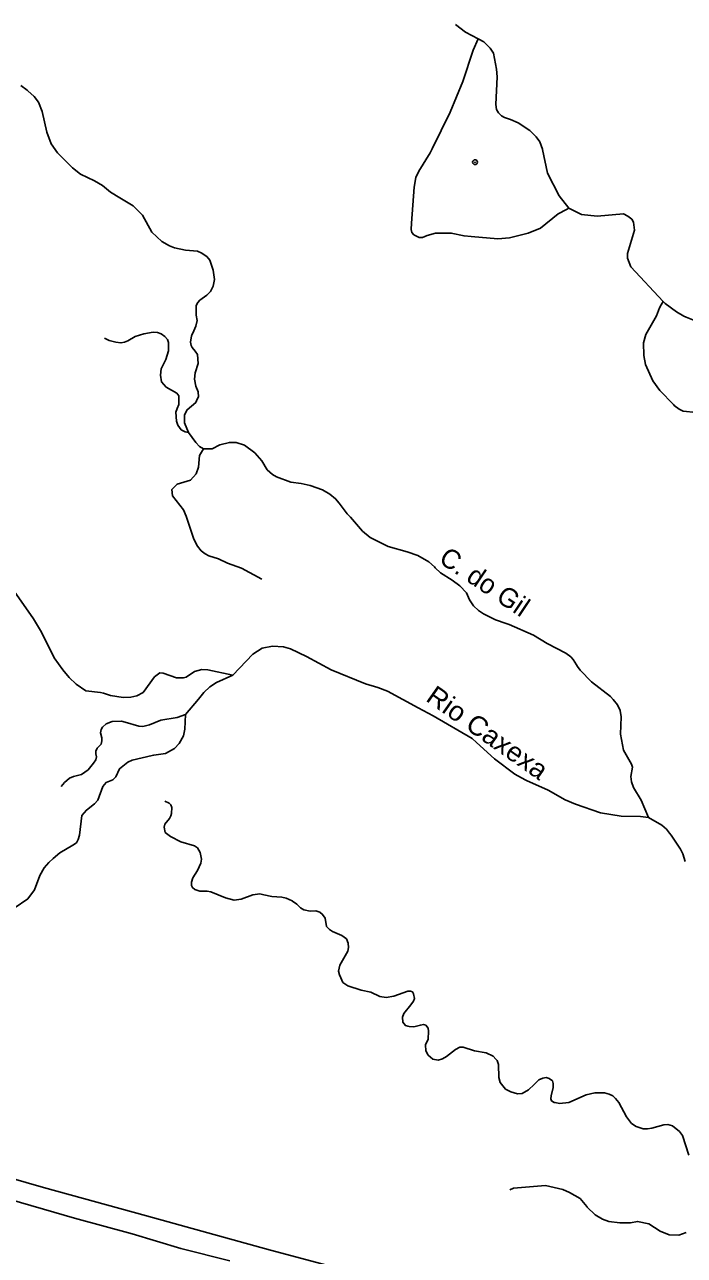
# Model space of a CAD drawing. Extents: x 267.7 to 296, y 7537.7 to 7565.8.
# Drawn here: x 270.43 to 273.16, y 7560.4 to 7565.5 of the extents above; entities that cross this region are included whole.
import ezdxf
from ezdxf.enums import TextEntityAlignment as Align

# ---------------------------------------------------------------- set-up
doc = ezdxf.new("R2010")
doc.units = 0
doc.header["$LTSCALE"] = 0.04
doc.header["$PDMODE"] = 32
doc.header["$PDSIZE"] = 0.02
doc.layers.add('1', color=7, linetype='Continuous', lineweight=25)
doc.layers.add('7', color=7, linetype='Continuous', lineweight=25)
doc.layers.add('54', color=7, linetype='Continuous')
doc.layers.add('61', color=7, linetype='Continuous')

msp = doc.modelspace()

# ---------------------------------------------------------------- linework, layer by layer
at = {"layer": '1'}
for points in [[(269.2121, 7561.0128), (269.2305, 7560.9925), (269.2633, 7560.9712), (269.4053, 7560.9017), (269.5415, 7560.8437), (269.6371, 7560.8099), (269.7646, 7560.778), (269.8438, 7560.7636), (269.9134, 7560.7578), (270.0882, 7560.7597), (270.2099, 7560.7481), (270.2891, 7560.7394), (270.3664, 7560.722), (270.5103, 7560.6815), (270.9372, 7560.5636), (271.1913, 7560.4931), (271.4501, 7560.4207), (271.787, 7560.3318)], [(270.3281, 7560.6436), (270.6385, 7560.5546), (270.8781, 7560.4889), (271.0795, 7560.4289), (271.2817, 7560.3773)]]:
    msp.add_lwpolyline(points, dxfattribs=at)
at = {"layer": '54'}
msp.add_point((272.2974, 7564.9283), dxfattribs=at)
at = {"layer": '7'}
for points in [[(272.2171, 7565.4981), (272.2574, 7565.4673), (272.3106, 7565.4393)], [(272.3106, 7565.4393), (272.2897, 7565.3918), (272.2464, 7565.2624), (272.1946, 7565.1352), (272.1198, 7564.9839), (272.1112, 7564.9666), (272.0648, 7564.8905), (272.0527, 7564.8651), (272.0452, 7564.8253), (272.0349, 7564.6754), (272.0329, 7564.6498), (272.036, 7564.6364), (272.0442, 7564.6272), (272.0657, 7564.6169), (272.08, 7564.6166), (272.0993, 7564.6251), (272.1343, 7564.6344), (272.1991, 7564.6348), (272.2518, 7564.6226), (272.2815, 7564.62), (272.3922, 7564.6101), (272.4407, 7564.6154), (272.5179, 7564.6345), (272.5681, 7564.6548), (272.6414, 7564.7145), (272.6759, 7564.7318), (272.6857, 7564.738)], [(272.3106, 7565.4393), (272.3342, 7565.4269), (272.3601, 7565.3999), (272.3733, 7565.3793), (272.3869, 7565.3138), (272.3893, 7565.2823), (272.3839, 7565.1671), (272.386, 7565.1465), (272.3942, 7565.1332), (272.4065, 7565.1209), (272.4188, 7565.1137), (272.4445, 7565.1055), (272.4763, 7565.0908), (272.5241, 7565.0596), (272.5511, 7565.0332), (272.5657, 7565.0123), (272.5772, 7564.9815), (272.5774, 7564.9811), (272.5978, 7564.8823), (272.6463, 7564.7888), (272.6857, 7564.738)], [(270.4159, 7565.2456), (270.4429, 7565.2259), (270.4455, 7565.224), (270.4716, 7565.2), (270.4894, 7565.1764), (270.5049, 7565.1377), (270.5236, 7565.0528), (270.5415, 7565.0039), (270.5679, 7564.9668), (270.6301, 7564.9053), (270.6639, 7564.8791), (270.7216, 7564.851), (270.7545, 7564.8314), (270.7881, 7564.8035), (270.8268, 7564.7805), (270.8815, 7564.7479), (270.9201, 7564.7085), (270.9591, 7564.639), (271.0003, 7564.6001), (271.0325, 7564.5815), (271.0527, 7564.5739), (271.0991, 7564.5638), (271.1477, 7564.5597), (271.1509, 7564.5584), (271.1635, 7564.5533), (271.1863, 7564.5372), (271.1995, 7564.5229), (271.2132, 7564.4805), (271.2179, 7564.4424), (271.2128, 7564.4147), (271.2015, 7564.3926), (271.1866, 7564.3775), (271.1571, 7564.3561), (271.1491, 7564.347), (271.1431, 7564.3346), (271.143, 7564.2946), (271.1461, 7564.2725), (271.1409, 7564.2484), (271.1336, 7564.2293), (271.1247, 7564.211), (271.1236, 7564.2087), (271.1191, 7564.1825), (271.1214, 7564.1694), (271.1266, 7564.1602), (271.1389, 7564.1448), (271.1477, 7564.1313), (271.1509, 7564.0946), (271.1385, 7564.056), (271.1358, 7564.0292), (271.1408, 7564.0007), (271.1508, 7563.9774), (271.1516, 7563.9566), (271.1472, 7563.9462), (271.1416, 7563.9329), (271.1055, 7563.9028), (271.0941, 7563.882), (271.0936, 7563.8484), (271.1106, 7563.8087)], [(272.6857, 7564.738), (272.719, 7564.721), (272.7387, 7564.711), (272.8037, 7564.705), (272.9117, 7564.7137), (272.93, 7564.7052), (272.9469, 7564.6915), (272.9531, 7564.6794), (272.9575, 7564.646), (272.9288, 7564.5494), (272.9291, 7564.5303), (272.9426, 7564.4949), (273.0769, 7564.3511)], [(273.0769, 7564.3511), (273.0675, 7564.3377), (273.0609, 7564.3243), (273.0491, 7564.2921), (273.0049, 7564.2149), (272.9943, 7564.1795), (272.9966, 7564.1269), (273.0033, 7564.0905), (273.0337, 7564.0219), (273.0626, 7563.9822), (273.1194, 7563.9241), (273.1225, 7563.9209), (273.1427, 7563.905), (273.1599, 7563.8968), (273.2137, 7563.8919)], [(273.0769, 7564.3511), (273.0852, 7564.3422), (273.1311, 7564.3079), (273.1617, 7564.291), (273.1713, 7564.2857), (273.2409, 7564.2583), (273.3691, 7564.23), (273.5033, 7564.2158), (273.5828, 7564.196), (273.6844, 7564.1868)], [(270.7624, 7564.1988), (270.7817, 7564.1899), (270.8104, 7564.1827), (270.831, 7564.1797), (270.8464, 7564.1827), (270.8592, 7564.1885), (270.89, 7564.2065), (270.9264, 7564.2176), (270.9646, 7564.2238), (270.9829, 7564.2228), (270.9971, 7564.2172), (271.0127, 7564.2064), (271.0239, 7564.194), (271.0278, 7564.1815), (271.028, 7564.1469), (271.0175, 7564.1102), (270.9977, 7564.0719), (270.9946, 7564.0454), (270.999, 7564.0185), (271.0177, 7563.9968), (271.0632, 7563.9713), (271.0708, 7563.96), (271.0711, 7563.925), (271.0645, 7563.9083), (271.0582, 7563.8922), (271.0607, 7563.8556), (271.066, 7563.8385), (271.0808, 7563.8193), (271.0965, 7563.8115), (271.1106, 7563.8087)], [(271.1106, 7563.8087), (271.1106, 7563.8086), (271.1406, 7563.7673), (271.1568, 7563.7503), (271.1734, 7563.7415)], [(271.1734, 7563.7415), (271.2086, 7563.7406), (271.2409, 7563.7577), (271.2806, 7563.7675), (271.3086, 7563.7675), (271.3424, 7563.7562), (271.3853, 7563.7246), (271.414, 7563.6911), (271.4372, 7563.6544), (271.4583, 7563.6347), (271.4747, 7563.6249), (271.5348, 7563.6032), (271.5772, 7563.5967), (271.6145, 7563.5884), (271.6661, 7563.5705), (271.6957, 7563.5531), (271.7198, 7563.534), (271.7348, 7563.5163), (271.7673, 7563.4716), (271.7814, 7563.4581), (271.8316, 7563.3996), (271.863, 7563.3731), (271.9374, 7563.3367), (272.0167, 7563.3147), (272.0599, 7563.2985), (272.1058, 7563.2723), (272.1294, 7563.2518), (272.1327, 7563.2485), (272.1538, 7563.2275), (272.2032, 7563.1964), (272.234, 7563.1727), (272.2615, 7563.1437), (272.2749, 7563.1154), (272.2917, 7563.0902), (272.3116, 7563.071), (272.3329, 7563.0569), (272.3817, 7563.0324), (272.4262, 7563.0176), (272.4382, 7563.0136), (272.5394, 7562.9694), (272.5965, 7562.9345), (272.6739, 7562.8943), (272.6939, 7562.8792), (272.7043, 7562.8684), (272.7182, 7562.8462), (272.7223, 7562.8397), (272.7321, 7562.824), (272.7798, 7562.7757), (272.8585, 7562.7149), (272.8689, 7562.7025), (272.8874, 7562.6803), (272.8982, 7562.6565), (272.9025, 7562.6308), (272.9001, 7562.5582), (272.9127, 7562.4925), (272.9451, 7562.434), (272.9488, 7562.4218), (272.9424, 7562.3833), (272.9455, 7562.3614), (272.9533, 7562.338)], [(271.4151, 7563.2004), (271.3301, 7563.246), (271.2725, 7563.2677), (271.2349, 7563.2857), (271.1956, 7563.2974), (271.1792, 7563.3053), (271.1638, 7563.3181), (271.1487, 7563.3378), (271.1332, 7563.3671), (271.1017, 7563.462), (271.0903, 7563.4881), (271.0448, 7563.5458), (271.0413, 7563.5722), (271.0635, 7563.595), (271.1195, 7563.6109), (271.1421, 7563.6366), (271.1525, 7563.6653), (271.1558, 7563.7127), (271.1734, 7563.7415)], [(270.3497, 7563.2064), (270.4684, 7563.0369), (270.5016, 7562.9819), (270.5552, 7562.8746), (270.59, 7562.8247), (270.6164, 7562.7932), (270.6455, 7562.7662), (270.6863, 7562.739), (270.7471, 7562.7309), (270.759, 7562.7293), (270.7874, 7562.7189), (270.8409, 7562.711), (270.8719, 7562.7125), (270.8972, 7562.7182), (270.9227, 7562.7317), (270.9701, 7562.7958), (270.9915, 7562.8127), (271.0057, 7562.8122), (271.0612, 7562.7925), (271.0903, 7562.7924), (271.1011, 7562.7955), (271.1362, 7562.8184), (271.1656, 7562.8273)], [(271.294, 7562.8034), (271.3777, 7562.8898), (271.4153, 7562.9148), (271.4586, 7562.9231), (271.5049, 7562.92), (271.5339, 7562.912), (271.5997, 7562.8812), (271.7012, 7562.8252), (271.8444, 7562.767), (271.8953, 7562.7519), (271.9354, 7562.7368), (272.0622, 7562.668), (272.1236, 7562.6347), (272.2859, 7562.5407), (272.3041, 7562.5242), (272.3785, 7562.4569), (272.4628, 7562.3934), (272.5048, 7562.3694), (272.5103, 7562.3663), (272.6, 7562.3271), (272.6705, 7562.2862), (272.7136, 7562.2685), (272.8168, 7562.2334), (272.9029, 7562.2188), (272.9828, 7562.2177), (273.0159, 7562.2134)], [(271.0978, 7562.6403), (271.1523, 7562.7034), (271.1743, 7562.7319), (271.1998, 7562.7551), (271.2272, 7562.773), (271.294, 7562.8034)], [(271.1656, 7562.8273), (271.1908, 7562.825), (271.294, 7562.8034)], [(270.3884, 7561.8381), (270.445, 7561.8765), (270.4738, 7561.9138), (270.4952, 7561.974), (270.5131, 7562.0052), (270.532, 7562.0272), (270.5498, 7562.0441), (270.578, 7562.0674), (270.6318, 7562.0988), (270.6468, 7562.109), (270.6539, 7562.1232), (270.6596, 7562.1403), (270.6698, 7562.2217), (270.6884, 7562.2444), (270.7218, 7562.2707), (270.7352, 7562.2858), (270.7554, 7562.3424), (270.7693, 7562.3583), (270.7979, 7562.37), (270.8096, 7562.3815), (270.8249, 7562.4159), (270.8593, 7562.4426), (270.8778, 7562.4514), (270.961, 7562.4709), (270.9666, 7562.4722), (271.0161, 7562.479), (271.0533, 7562.5), (271.0725, 7562.5208), (271.0895, 7562.5513), (271.0958, 7562.5801), (271.0978, 7562.6403)], [(270.5836, 7562.3424), (270.598, 7562.3588), (270.6186, 7562.376), (270.6348, 7562.3834), (270.6681, 7562.392), (270.695, 7562.4105), (270.717, 7562.4386), (270.7273, 7562.4532), (270.7304, 7562.4656), (270.7273, 7562.4779), (270.7273, 7562.4881), (270.7324, 7562.5004), (270.7488, 7562.5179), (270.7519, 7562.5306), (270.7519, 7562.5438), (270.7464, 7562.5641), (270.7488, 7562.5786), (270.7546, 7562.5883), (270.7698, 7562.6018), (270.7946, 7562.6119), (270.8333, 7562.6127), (270.8488, 7562.608), (270.9048, 7562.5913), (270.9213, 7562.5905), (270.949, 7562.5981), (270.9962, 7562.6172), (271.0637, 7562.6281), (271.0978, 7562.6403)], [(272.9533, 7562.338), (272.9854, 7562.2848), (273.0159, 7562.2134)], [(271.0132, 7562.2812), (271.0311, 7562.2729), (271.0373, 7562.2664), (271.0414, 7562.2551), (271.0403, 7562.2305), (271.0383, 7562.2202), (271.0321, 7562.21), (271.0122, 7562.1856), (271.0096, 7562.174), (271.0139, 7562.1521), (271.0357, 7562.1347), (271.0794, 7562.1123), (271.1362, 7562.0967), (271.1485, 7562.0877), (271.1592, 7562.0687), (271.1653, 7562.041), (271.1625, 7562.0243), (271.1625, 7562.0242), (271.1475, 7561.9938), (271.1291, 7561.9634), (271.1239, 7561.9455), (271.1239, 7561.9324), (271.1277, 7561.923), (271.1366, 7561.9148), (271.1577, 7561.9089), (271.1882, 7561.9082), (271.203, 7561.9064), (271.2637, 7561.8806), (271.3006, 7561.8715), (271.3294, 7561.8753), (271.3779, 7561.8939), (271.4056, 7561.897), (271.4222, 7561.8938), (271.456, 7561.8858), (271.4973, 7561.8834), (271.5156, 7561.8795), (271.54, 7561.8684), (271.5415, 7561.8674), (271.559, 7561.8553), (271.575, 7561.8392), (271.5887, 7561.8314), (271.6149, 7561.8258), (271.6387, 7561.8271), (271.6552, 7561.822), (271.6663, 7561.8123), (271.6767, 7561.7969), (271.6828, 7561.7625), (271.6952, 7561.7501), (271.7076, 7561.7408), (271.7462, 7561.7254), (271.7654, 7561.7107), (271.7722, 7561.6927), (271.7734, 7561.6746), (271.7702, 7561.6595), (271.7376, 7561.602), (271.7322, 7561.5777), (271.7363, 7561.5613), (271.7414, 7561.5496), (271.7498, 7561.5306), (271.7712, 7561.5167), (271.8265, 7561.4984), (271.8663, 7561.4899), (271.9031, 7561.4728), (271.9296, 7561.4682), (271.9613, 7561.4732), (272.0191, 7561.4948), (272.03, 7561.4946), (272.0382, 7561.4908), (272.0431, 7561.4833), (272.0461, 7561.4642), (272.0421, 7561.4535), (272.0322, 7561.4381), (272.0031, 7561.4014), (271.9976, 7561.3867), (271.9984, 7561.3653), (272.0093, 7561.3519), (272.0194, 7561.3492), (272.0247, 7561.3478), (272.0437, 7561.3465), (272.0709, 7561.3539), (272.0846, 7561.356), (272.0934, 7561.3529), (272.1027, 7561.3416), (272.1053, 7561.3288), (272.1029, 7561.2958), (272.0926, 7561.2714), (272.0938, 7561.2475), (272.1035, 7561.2294), (272.1232, 7561.213), (272.1447, 7561.2091), (272.1633, 7561.2143), (272.1793, 7561.2233), (272.2165, 7561.2532), (272.2351, 7561.2616), (272.2489, 7561.2618)], [(273.0159, 7562.2134), (273.0708, 7562.1818), (273.0901, 7562.1648), (273.1025, 7562.1494), (273.1089, 7562.1399), (273.1476, 7562.0826), (273.1578, 7562.0629)], [(273.1578, 7562.0629), (273.1673, 7562.031)], [(272.2489, 7561.2618), (272.2949, 7561.2475), (272.3431, 7561.2394), (272.3724, 7561.2247), (272.3835, 7561.213), (272.3891, 7561.2071)], [(272.3891, 7561.2071), (272.3941, 7561.19), (272.3958, 7561.1361), (272.4017, 7561.116), (272.424, 7561.0882), (272.4455, 7561.0774), (272.4736, 7561.0696), (272.493, 7561.0697), (272.5187, 7561.0853), (272.542, 7561.1077), (272.5621, 7561.127), (272.5784, 7561.1334), (272.5923, 7561.1363), (272.6048, 7561.1325), (272.6179, 7561.1227), (272.6215, 7561.1115), (272.6214, 7561.0952), (272.6128, 7561.0604), (272.6118, 7561.0482), (272.6118, 7561.0481), (272.6138, 7561.0399), (272.6251, 7561.0337), (272.6291, 7561.0328), (272.6474, 7561.0288), (272.6851, 7561.0326), (272.7581, 7561.0652), (272.7934, 7561.0728), (272.833, 7561.0727)], [(272.833, 7561.0727), (272.853, 7561.0676), (272.8674, 7561.0604), (272.8793, 7561.0495), (272.8922, 7561.0325), (272.9246, 7560.9732), (272.9458, 7560.9464), (272.9652, 7560.9332), (272.9939, 7560.9244), (273.0109, 7560.9235), (273.0295, 7560.927), (273.0788, 7560.941), (273.0963, 7560.9413), (273.1147, 7560.9362), (273.1439, 7560.9134), (273.157, 7560.8968), (273.1826, 7560.8146)], [(272.4413, 7560.6707), (272.4572, 7560.6783), (272.5885, 7560.6889), (272.6603, 7560.673), (272.6891, 7560.6603), (272.7322, 7560.6348), (272.7597, 7560.602), (272.7615, 7560.5999), (272.7947, 7560.568), (272.8258, 7560.5497), (272.8517, 7560.5403), (272.8968, 7560.5341), (272.9407, 7560.5349), (272.97, 7560.5404), (273.0173, 7560.5305), (273.0641, 7560.4999), (273.1015, 7560.4854), (273.1418, 7560.4838), (273.1717, 7560.494)]]:
    msp.add_lwpolyline(points, dxfattribs=at)

# ---------------------------------------------------------------- texts
at = {"layer": '61'}
msp.add_text('C. do Gil', height=0.08, rotation=326.13, dxfattribs=at).set_placement((272.3153, 7563.1571), align=Align.CENTER)
at = {"layer": '61', "width": 1.05}
msp.add_text('Rio Caxexa', height=0.08, rotation=324.848, dxfattribs=at).set_placement((272.3263, 7562.5326), align=Align.CENTER)

doc.saveas('drawing.dxf')
